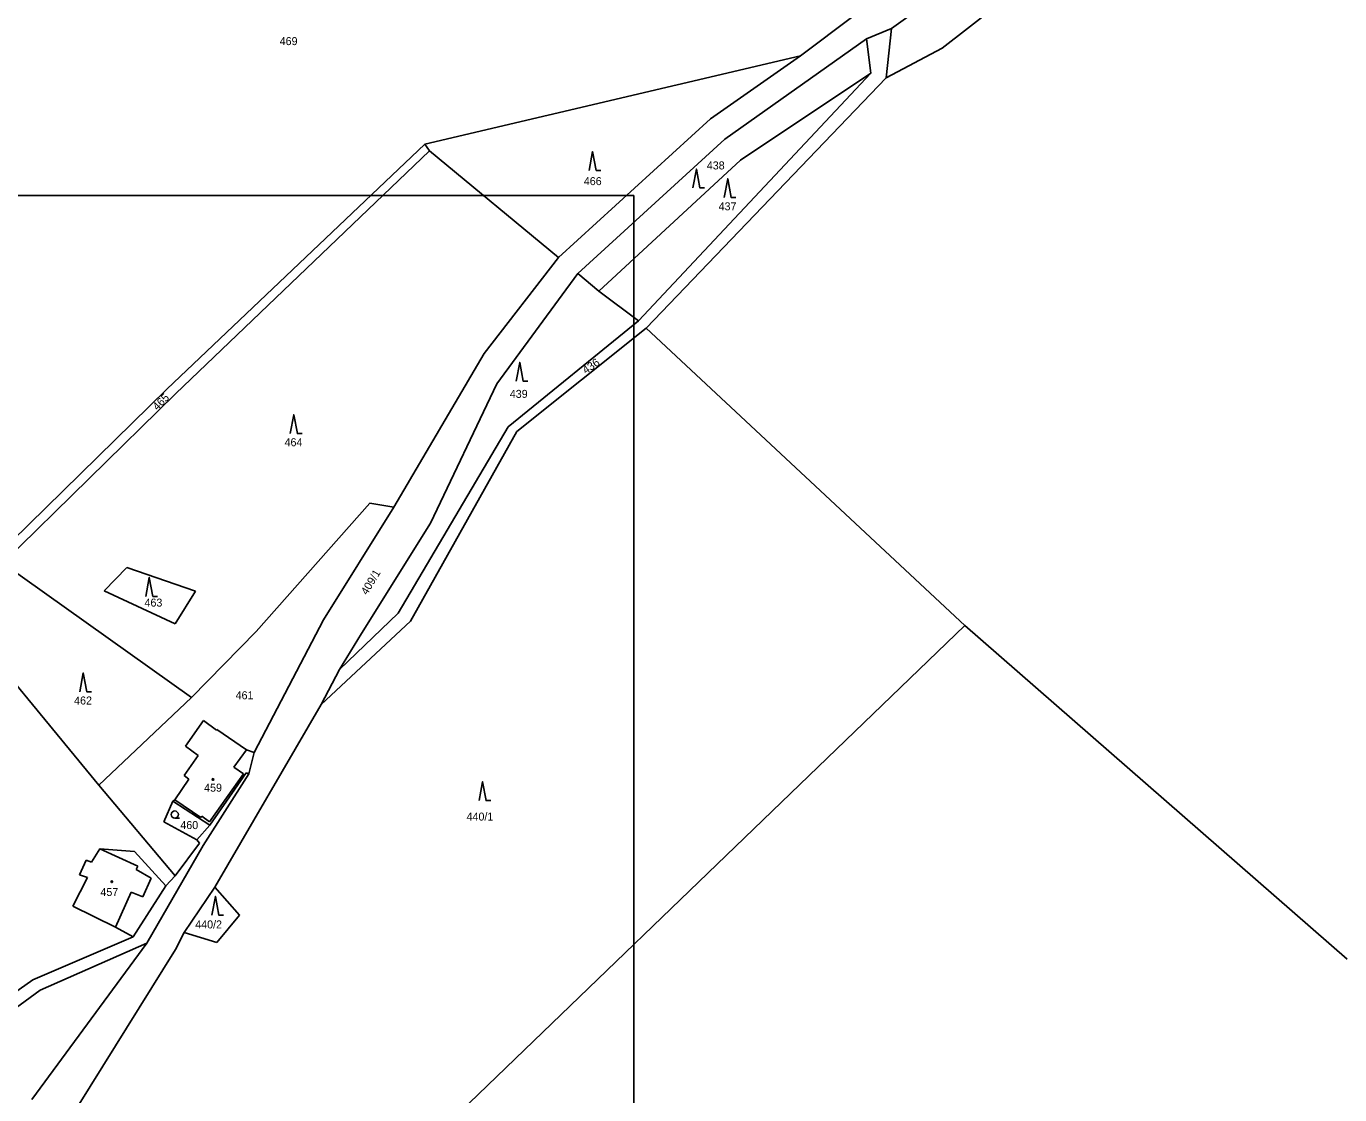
# Model space of a CAD drawing. Extents: x -670359 to -668019, y -978807 to -976674.
# Drawn here: x -668879.1 to -668600.1, y -977190.9 to -976964 of the extents above; entities that cross this region are included whole.
import ezdxf

# ---------------------------------------------------------------- set-up
doc = ezdxf.new("R2010")
doc.units = 0
for name, color, linetype in [('Hranice parcel', 7, 'Continuous'), ('ML1000', 7, 'Continuous'), ('Parcelní čísla', 7, 'Continuous'), ('Vnitřní kresba', 7, 'Continuous'), ('Značky budov', 7, 'Continuous'), ('Značky kultur', 7, 'Continuous')]:
    doc.layers.add(name, color=color, linetype=linetype)

msp = doc.modelspace()

# ---------------------------------------------------------------- linework, layer by layer
at = {"layer": 'Hranice parcel'}
for p, q in [((-668845.26, -977116.88), (-668841.44, -977111.49)), ((-668841.44, -977111.49), (-668838.7, -977113.52)), ((-668838.7, -977113.52), (-668838.62, -977113.38)), ((-668838.62, -977113.38), (-668832.31, -977117.72)), ((-668842.53, -977118.88), (-668845.26, -977116.88)), ((-668832.31, -977117.72), (-668830.7, -977118.27)), ((-668845.51, -977123.16), (-668842.53, -977118.88)), ((-668844.52, -977123.88), (-668845.51, -977123.16)), ((-668832.36, -977122.59), (-668840.12, -977133.69)), ((-668832.36, -977122.59), (-668831.83, -977122.75)), ((-668847.54, -977128.33), (-668844.52, -977123.88)), ((-668847.94, -977128.62), (-668847.54, -977128.33)), ((-668840.12, -977133.69), (-668847.94, -977128.62)), ((-668842.85, -977136.8), (-668840.12, -977133.69))]:
    msp.add_line(p, q, dxfattribs=at)
for points in [[(-668695.31, -976964.49), (-668670, -976946.29)], [(-668703.22, -976961.78), (-668714.63, -976970.3)], [(-668684.58, -976968.68), (-668673.18, -976959.83)], [(-668695.31, -976964.49), (-668700.61, -976966.72)], [(-668696.47, -976975), (-668695.31, -976964.49)], [(-668700.61, -976966.72), (-668730.68, -976987.99)], [(-668699.68, -976974.03), (-668700.61, -976966.72)], [(-668794.4, -976989.09), (-668714.63, -976970.3)], [(-668714.63, -976970.3), (-668733.72, -976983.72)], [(-668696.47, -976975), (-668684.58, -976968.68)], [(-668749.05, -977026.61), (-668699.68, -976974.03)], [(-668747.41, -977028.17), (-668696.47, -976975)], [(-668727.38, -976992.48), (-668699.68, -976974.03)], [(-668733.72, -976983.72), (-668766, -977013.17)], [(-668794.4, -976989.09), (-668849.2, -977041.1)], [(-668793.42, -976990.46), (-668794.4, -976989.09)], [(-668730.68, -976987.99), (-668761.9, -977016.56)], [(-668793.42, -976990.46), (-668847.36, -977042.09)], [(-668766, -977013.17), (-668793.42, -976990.46)], [(-668757.46, -977020.32), (-668727.38, -976992.48)], [(-668766, -977013.17), (-668781.85, -977033.56)], [(-668761.9, -977016.56), (-668779.14, -977039.94)], [(-668761.9, -977016.56), (-668757.46, -977020.32)], [(-668757.46, -977020.32), (-668749.05, -977026.61)], [(-668776.71, -977049.07), (-668749.05, -977026.61)], [(-668774.87, -977050.06), (-668747.41, -977028.17)], [(-668679.76, -977091.25), (-668747.41, -977028.17)], [(-668781.85, -977033.56), (-668800.98, -977066.19)], [(-668779.14, -977039.94), (-668793.22, -977069.57)], [(-668847.36, -977042.09), (-668884.04, -977078.04)], [(-668849.2, -977041.1), (-668882.19, -977073.48)], [(-668800.09, -977088.67), (-668776.71, -977049.07)], [(-668797.45, -977090.36), (-668774.87, -977050.06)], [(-668806.1, -977065.29), (-668830.21, -977092.59)], [(-668815.95, -977090.07), (-668800.98, -977066.19)], [(-668800.98, -977066.19), (-668806.1, -977065.29)], [(-668793.22, -977069.57), (-668807.87, -977092.97)], [(-668843.95, -977106.55), (-668884.04, -977078.04)], [(-668862.53, -977083.94), (-668857.71, -977078.99)], [(-668857.71, -977078.99), (-668843.15, -977083.99)], [(-668847.42, -977090.94), (-668862.53, -977083.94)], [(-668843.15, -977083.99), (-668847.42, -977090.94)], [(-668863.63, -977125.22), (-668895.52, -977086.57)], [(-668830.7, -977118.27), (-668815.95, -977090.07)], [(-668812.54, -977100.64), (-668800.09, -977088.67)], [(-668830.21, -977092.59), (-668843.95, -977106.55)], [(-668679.76, -977091.25), (-668818.16, -977224.64)], [(-668816.41, -977108.07), (-668797.45, -977090.36)], [(-668807.87, -977092.97), (-668812.54, -977100.64)], [(-668598.5, -977162.16), (-668679.76, -977091.25)], [(-668812.54, -977100.64), (-668816.41, -977108.07)], [(-668843.95, -977106.55), (-668863.63, -977125.22)], [(-668816.41, -977108.07), (-668839.05, -977146.84)], [(-668831.83, -977122.75), (-668830.7, -977118.27)], [(-668831.83, -977122.75), (-668841.49, -977138)], [(-668863.63, -977125.22), (-668847.44, -977144.47)], [(-668849.88, -977132.94), (-668847.94, -977128.62)], [(-668842.85, -977136.8), (-668849.88, -977132.94)], [(-668847.44, -977144.47), (-668842.29, -977137.52)], [(-668842.29, -977137.52), (-668842.85, -977136.8)], [(-668863.43, -977138.74), (-668865.2, -977141.54)], [(-668856.07, -977139.24), (-668863.43, -977138.74)], [(-668849.45, -977146.54), (-668856.07, -977139.24)], [(-668841.49, -977138), (-668853.49, -977158.77)], [(-668866.32, -977141.14), (-668867.77, -977144.25)], [(-668865.2, -977141.54), (-668866.32, -977141.14)], [(-668866.09, -977144.82), (-668869.16, -977150.89)], [(-668867.77, -977144.25), (-668866.09, -977144.82)], [(-668847.44, -977144.47), (-668849.45, -977146.54)], [(-668849.45, -977146.54), (-668856.37, -977157.4)], [(-668839.05, -977146.84), (-668845.55, -977156.5)], [(-668839.05, -977146.84), (-668833.76, -977152.81)], [(-668869.16, -977150.89), (-668860.12, -977155.31)], [(-668833.76, -977152.81), (-668838.59, -977158.61)], [(-668860.12, -977155.31), (-668856.37, -977157.4)], [(-668845.55, -977156.5), (-668847.41, -977160.07)], [(-668838.59, -977158.61), (-668845.55, -977156.5)], [(-668853.49, -977158.77), (-668877.86, -977191.91)], [(-668856.37, -977157.4), (-668877.7, -977166.55)], [(-668853.49, -977158.77), (-668876.1, -977168.71)], [(-668847.41, -977160.07), (-668880.9, -977213.98)], [(-668877.7, -977166.55), (-668911.08, -977190.06)], [(-668876.1, -977168.71), (-668907.97, -977191.98)]]:
    msp.add_lwpolyline(points, dxfattribs=at)
at = {"layer": 'ML1000'}
msp.add_lwpolyline([(-668750, -977000), (-668750, -977500), (-669375, -977500), (-669375, -977000)], close=True, dxfattribs=at)
at = {"layer": 'Vnitřní kresba'}
for p, q in [((-668832.31, -977117.72), (-668835, -977121.37)), ((-668832.95, -977122.77), (-668840.14, -977132.95)), ((-668835, -977121.37), (-668832.95, -977122.77)), ((-668841.97, -977132.07), (-668847.54, -977128.33)), ((-668841.76, -977131.78), (-668841.97, -977132.07)), ((-668840.14, -977132.95), (-668841.76, -977131.78))]:
    msp.add_line(p, q, dxfattribs=at)
for points in [[(-668863.43, -977138.74), (-668855.36, -977142.37)], [(-668855.36, -977142.37), (-668855.76, -977143.08)], [(-668855.76, -977143.08), (-668852.56, -977144.93)], [(-668852.56, -977144.93), (-668854.34, -977148.93)], [(-668856.82, -977147.88), (-668860.12, -977155.31)], [(-668854.34, -977148.93), (-668856.82, -977147.88)]]:
    msp.add_lwpolyline(points, dxfattribs=at)
at = {"layer": 'Značky budov'}
for centre in [(-668839.41, -977123.97), (-668860.9, -977145.69)]:
    msp.add_circle(centre, 0.175, dxfattribs=at)
at = {"layer": 'Značky kultur'}
msp.add_line((-668847.52, -977132.17), (-668846.52, -977132.17), dxfattribs=at)
for points in [[(-668759.53, -976994.66), (-668758.78, -976990.66), (-668758.03, -976994.66), (-668757.03, -976994.66)], [(-668737.5, -976998.37), (-668736.75, -976994.37), (-668736, -976998.37), (-668735, -976998.37)], [(-668730.85, -977000.42), (-668730.1, -976996.42), (-668729.35, -977000.42), (-668728.35, -977000.42)], [(-668775.03, -977039.42), (-668774.28, -977035.42), (-668773.53, -977039.42), (-668772.53, -977039.42)], [(-668823, -977050.52), (-668822.25, -977046.52), (-668821.5, -977050.52), (-668820.5, -977050.52)], [(-668853.69, -977085.09), (-668852.94, -977081.09), (-668852.19, -977085.09), (-668851.19, -977085.09)], [(-668867.73, -977105.36), (-668866.98, -977101.36), (-668866.23, -977105.36), (-668865.23, -977105.36)], [(-668782.9, -977128.47), (-668782.15, -977124.47), (-668781.4, -977128.47), (-668780.4, -977128.47)], [(-668839.66, -977152.8), (-668838.91, -977148.8), (-668838.16, -977152.8), (-668837.16, -977152.8)]]:
    msp.add_lwpolyline(points, dxfattribs=at)
for centre, radius in [((-668839.41, -977123.97), 0.175), ((-668847.52, -977131.42), 0.75), ((-668860.9, -977145.69), 0.175)]:
    msp.add_circle(centre, radius, dxfattribs=at)

# ---------------------------------------------------------------- texts
at = {"layer": 'Parcelní čísla'}
for s, p in [('469', (-668825.25, -976968.04)), ('438', (-668734.54, -976994.44)), ('466', (-668760.66, -976997.77)), ('437', (-668732.03, -977003.12)), ('439', (-668776.38, -977042.95)), ('464', (-668824.21, -977053.22)), ('463', (-668853.96, -977087.27)), ('462', (-668868.91, -977108.06)), ('461', (-668834.61, -977106.95)), ('459', (-668841.3, -977126.57)), ('440/1', (-668785.56, -977132.71)), ('460', (-668846.35, -977134.51)), ('457', (-668863.32, -977148.72)), ('440/2', (-668843.19, -977155.61))]:
    msp.add_text(s, height=1.7, dxfattribs=at).set_placement(p)
for s, rotation, p in [('436', 34.5923, (-668760.23, -977037.96)), ('465', 45, (-668851.24, -977045.73)), ('409/1', 58.9433, (-668806.68, -977084.93))]:
    msp.add_text(s, height=1.7, rotation=rotation, dxfattribs=at).set_placement(p)

doc.saveas('drawing.dxf')
